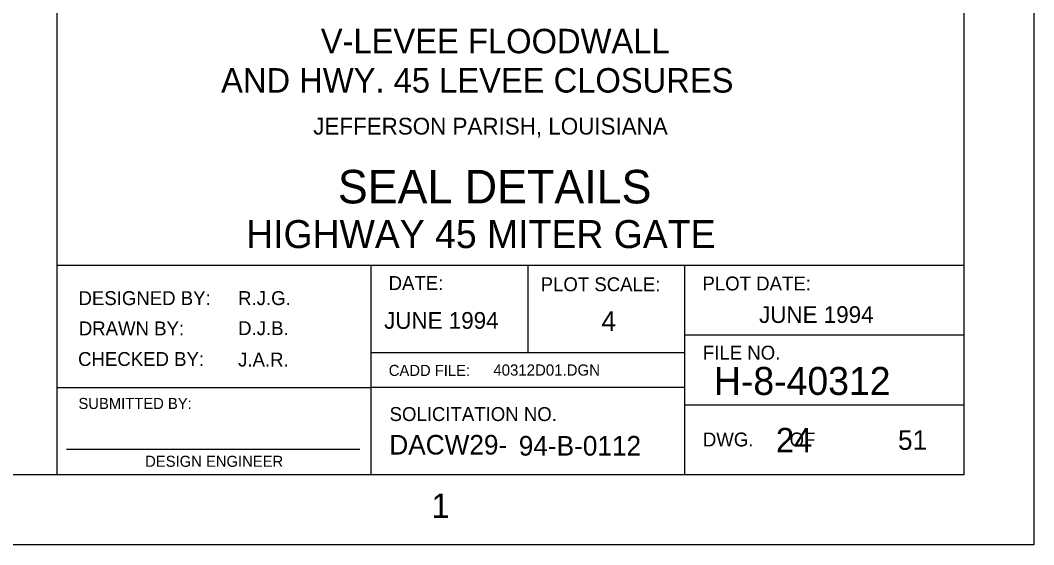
# Model space of a CAD drawing. Extents: x 0.1 to 13.5, y 0.1 to 9.5.
# Drawn here: x 11.037 to 13.458, y 0.125 to 1.377 of the extents above; entities that cross this region are included whole.
import ezdxf

# ---------------------------------------------------------------- set-up
doc = ezdxf.new("R2010")
doc.units = 0
doc.layers.add('Level 1', color=7, linetype='Continuous')
doc.layers.add('Level 2', color=7, linetype='Continuous')

msp = doc.modelspace()

# ---------------------------------------------------------------- linework, layer by layer
at = {"layer": 'Level 1'}
for p, q in [((11.125, 0.2917), (11.125, 1.875)), ((13.2917, 0.7917), (11.125, 0.7917)), ((11.875, 0.2917), (11.875, 0.7917)), ((12.25, 0.5833), (12.25, 0.7917)), ((12.625, 0.2917), (12.625, 0.7917)), ((13.2917, 0.625), (12.625, 0.625)), ((12.625, 0.5833), (11.875, 0.5833)), ((11.125, 0.5), (11.875, 0.5)), ((12.625, 0.5), (11.875, 0.5)), ((13.2917, 0.4583), (12.625, 0.4583)), ((11.1474, 0.3528), (11.8484, 0.3528))]:
    msp.add_line(p, q, dxfattribs=at)
for points in [[(0.125, 9.4583), (13.4583, 9.4583), (13.4583, 0.125), (0.125, 0.125)], [(0.625, 9.2917), (13.2917, 9.2917), (13.2917, 0.2917), (0.625, 0.2917)]]:
    msp.add_lwpolyline(points, close=True, dxfattribs=at)

# ---------------------------------------------------------------- texts
for s, height, p in [('DATE:', 0.03321, (11.917, 0.7329)), ('PLOT SCALE:', 0.033208, (12.2802, 0.73)), ('PLOT DATE:', 0.03321, (12.6668, 0.7319)), ('DESIGNED BY:', 0.033208, (11.176, 0.6969)), ('DRAWN BY:', 0.03321, (11.1767, 0.6247)), ('CHECKED BY:', 0.033208, (11.175, 0.5516)), ('FILE NO.', 0.03321, (12.6678, 0.5667)), ('CADD FILE:', 0.02642, (11.9173, 0.5278)), ('SUBMITTED BY:', 0.026417, (11.1758, 0.4489)), ('SOLICITATION NO.', 0.033208, (11.9193, 0.4202)), ('DACW29-', 0.04679, (11.9187, 0.3402)), ('DWG.       OF', 0.033208, (12.6678, 0.3595)), ('DESIGN ENGINEER', 0.026417, (11.3353, 0.3109)), ('1', 0.0584, (12.0192, 0.1887))]:
    msp.add_text(s, height=height, dxfattribs=at).set_placement(p)
at = {"layer": 'Level 2'}
for s, height, p in [('V-LEVEE FLOODWALL', 0.058417, (11.7549, 1.2979)), ('AND HWY. 45 LEVEE CLOSURES', 0.058417, (11.5167, 1.2041)), ('JEFFERSON PARISH, LOUISIANA', 0.04, (11.7368, 1.104)), ('SEAL DETAILS', 0.08, (11.7957, 0.9396)), ('HIGHWAY 45 MITER GATE', 0.066792, (11.5765, 0.833)), ('R.J.G.', 0.03321, (11.5573, 0.697)), ('JUNE 1994', 0.04, (11.9062, 0.6403)), ('4', 0.0468, (12.4254, 0.6354)), ('JUNE 1994', 0.04, (12.8021, 0.6543)), ('D.J.B.', 0.03321, (11.5573, 0.6252)), ('J.A.R.', 0.03321, (11.5573, 0.5502)), ('40312D01.DGN', 0.026792, (12.1671, 0.5285)), ('H-8-40312', 0.06679, (12.6942, 0.4825)), ('24', 0.05842, (12.8423, 0.3454)), ('51', 0.04679, (13.1341, 0.3515)), ('94-B-0112', 0.04679, (12.228, 0.3377))]:
    msp.add_text(s, height=height, dxfattribs=at).set_placement(p)

doc.saveas('drawing.dxf')
